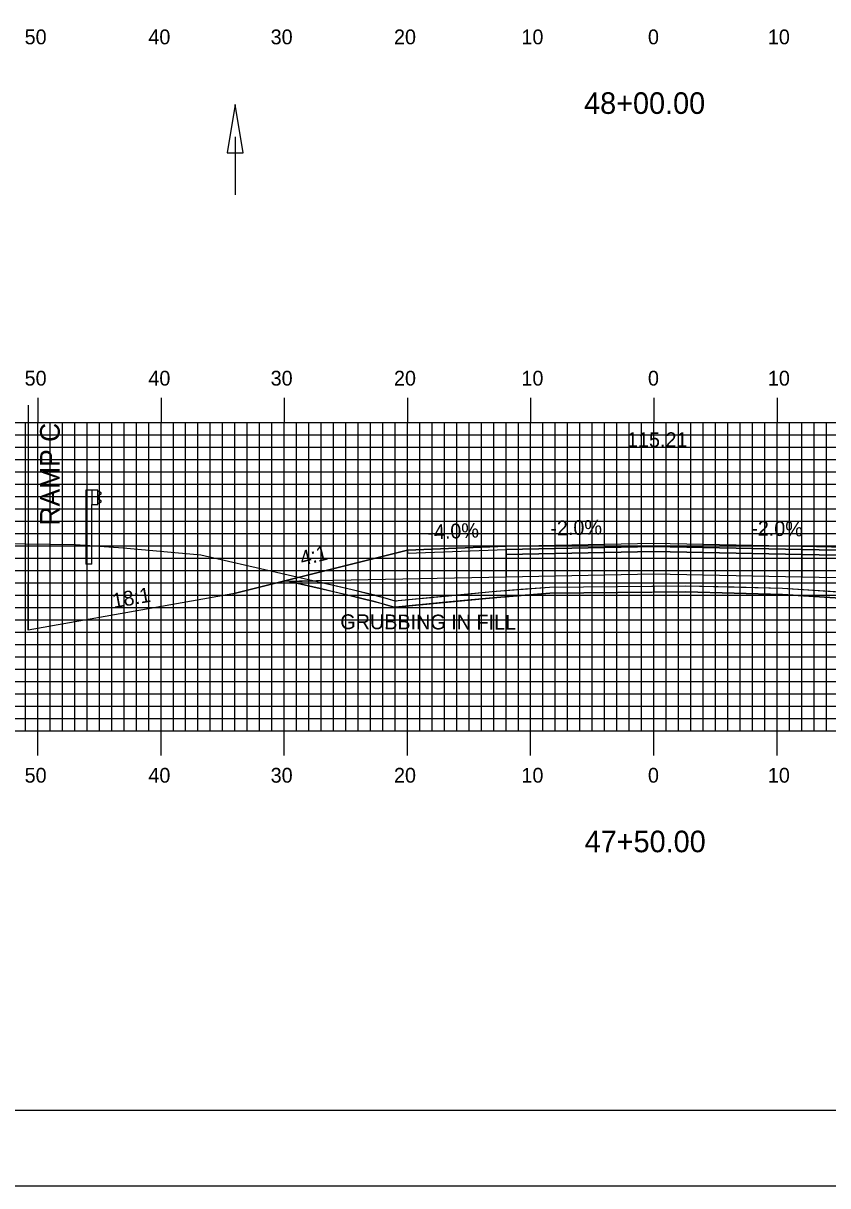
# Model space of a CAD drawing. Extents: x 1754708 to 1755051, y 442591 to 442811.
# Drawn here: x 1754822.3 to 1754887.6, y 442590.5 to 442684.8 of the extents above; entities that cross this region are included whole.
import ezdxf

# ---------------------------------------------------------------- set-up
doc = ezdxf.new("R2010")
doc.units = 0
for name, color, linetype in [('ANNOTATION', 7, 'Continuous'), ('BORDER', 7, 'Continuous'), ('D_Drainage_Ditch_Line', 7, 'Continuous'), ('D_Roadway_Centerline', 7, 'Continuous'), ('D_Roadway_Centerline_Text', 7, 'Continuous'), ('D_Roadway_Edge_Shoulder', 7, 'Continuous'), ('D_Roadway_Edge_TW', 7, 'Continuous'), ('D_Roadway_Pavement', 7, 'Continuous'), ('D_Roadway_SlopeLines', 7, 'Continuous'), ('D_Roadway_SubGrade', 7, 'Continuous'), ('GRUBBING IN FILL', 7, 'Continuous'), ('H_V ANNOTATION', 7, 'Continuous'), ('M_Guardrail', 7, 'Continuous'), ('MAJOR', 7, 'Continuous'), ('MINOR', 7, 'Continuous'), ('PLOT BOUNDARY', 7, 'Continuous'), ('S_Roadway_Centerline', 7, 'Continuous')]:
    doc.layers.add(name, color=color, linetype=linetype)

msp = doc.modelspace()

# ---------------------------------------------------------------- linework, layer by layer
at = {"layer": 'BORDER'}
msp.add_lwpolyline([(1754723.917, 442596.665), (1755043.917, 442596.665), (1755043.917, 442806.665), (1754723.917, 442806.665)], close=True, dxfattribs=at)
at = {"layer": 'D_Drainage_Ditch_Line'}
msp.add_line((1754839.529, 442675.611), (1754839.529, 442670.912), dxfattribs=at)
msp.add_lwpolyline([(1754838.873, 442674.298), (1754840.185, 442674.298), (1754839.529, 442678.235)], close=True, dxfattribs=at)
at = {"layer": 'D_Roadway_Centerline'}
msp.add_lwpolyline([(1754839.343, 442638.54), (1754843.343, 442639.54), (1754853.517, 442642.083), (1754861.517, 442642.403), (1754873.517, 442642.643), (1754885.517, 442642.403), (1754893.917, 442642.235), (1754901.917, 442641.915)], dxfattribs=at)
at = {"layer": 'D_Roadway_Edge_Shoulder'}
msp.add_lwpolyline([(1754861.517, 442642.403), (1754853.517, 442642.083), (1754853.517, 442641.833), (1754861.517, 442642.153)], close=True, dxfattribs=at)
at = {"layer": 'D_Roadway_Edge_TW'}
for points in [[(1754861.517, 442642.153), (1754861.517, 442642.403), (1754873.517, 442642.643), (1754885.517, 442642.403), (1754885.517, 442642.153), (1754873.517, 442642.393)], [(1754885.517, 442642.403), (1754893.917, 442642.235), (1754893.917, 442641.985), (1754885.517, 442642.153)]]:
    msp.add_lwpolyline(points, close=True, dxfattribs=at)
at = {"layer": 'D_Roadway_Pavement'}
for points in [[(1754861.517, 442641.736), (1754861.517, 442642.153), (1754873.517, 442642.393), (1754885.517, 442642.153), (1754885.517, 442641.736), (1754873.517, 442641.976)], [(1754885.517, 442642.153), (1754893.917, 442641.985), (1754893.917, 442641.568), (1754885.517, 442641.736)]]:
    msp.add_lwpolyline(points, close=True, dxfattribs=at)
at = {"layer": 'D_Roadway_SlopeLines'}
for p, q in [((1754822.747, 442635.606), (1754822.747, 442639.324)), ((1754839.343, 442638.54), (1754822.747, 442635.606))]:
    msp.add_line(p, q, dxfattribs=at)
msp.add_lwpolyline([(1754853.517, 442642.083), (1754839.343, 442638.54)], dxfattribs=at)
at = {"layer": 'D_Roadway_SubGrade'}
msp.add_line((1754822.747, 442653.844), (1754822.747, 442635.606), dxfattribs=at)
for points in [[(1754853.517, 442641.833), (1754861.517, 442642.153), (1754861.517, 442641.736), (1754861.517, 442639.903), (1754843.343, 442639.54), (1754853.517, 442642.083)], [(1754861.517, 442639.903), (1754861.517, 442641.736), (1754873.517, 442641.976), (1754885.517, 442641.736), (1754885.517, 442639.903), (1754873.517, 442640.143)], [(1754885.517, 442641.736), (1754893.917, 442641.568), (1754893.917, 442639.735), (1754885.517, 442639.903)]]:
    msp.add_lwpolyline(points, close=True, dxfattribs=at)
at = {"layer": 'GRUBBING IN FILL'}
for points in [[(1754843.956, 442639.552), (1754846.013, 442639.593), (1754849.044, 442638.898), (1754851.669, 442638.218), (1754852.494, 442637.976), (1754852.634, 442637.99), (1754852.774, 442638.004), (1754856.585, 442638.369), (1754860.396, 442638.734), (1754862.719, 442638.913), (1754865.043, 442639.092), (1754870.584, 442639.149), (1754873.517, 442639.179), (1754873.517, 442638.679), (1754870.592, 442638.649), (1754865.065, 442638.592), (1754862.752, 442638.414), (1754860.439, 442638.236), (1754856.631, 442637.871), (1754852.823, 442637.507), (1754852.447, 442637.469), (1754851.58, 442637.723), (1754846.442, 442638.982)], [(1754843.956, 442639.552), (1754846.013, 442639.593), (1754849.044, 442638.898), (1754851.669, 442638.218), (1754852.494, 442637.976), (1754852.634, 442637.99), (1754852.774, 442638.004), (1754856.585, 442638.369), (1754860.396, 442638.734), (1754862.719, 442638.913), (1754865.043, 442639.092), (1754870.584, 442639.149), (1754873.517, 442639.179), (1754873.517, 442638.679), (1754870.592, 442638.649), (1754865.065, 442638.592), (1754862.752, 442638.414), (1754860.439, 442638.236), (1754856.631, 442637.871), (1754852.823, 442637.507), (1754852.447, 442637.469), (1754851.58, 442637.723), (1754846.442, 442638.982)], [(1754873.517, 442639.179), (1754876.124, 442639.205), (1754880.045, 442639.102), (1754883.966, 442638.999), (1754889.322, 442638.663), (1754894.679, 442638.328), (1754899.258, 442637.968), (1754903.837, 442637.608), (1754910.777, 442637.359), (1754914.492, 442637.226), (1754914.492, 442636.725), (1754909.15, 442636.917), (1754903.808, 442637.109), (1754899.226, 442637.469), (1754894.644, 442637.829), (1754883.943, 442638.499), (1754880.032, 442638.602), (1754876.12, 442638.705), (1754873.517, 442638.679)], [(1754873.517, 442639.179), (1754876.124, 442639.205), (1754880.045, 442639.102), (1754883.966, 442638.999), (1754889.322, 442638.663), (1754894.679, 442638.328), (1754899.258, 442637.968), (1754903.837, 442637.608), (1754910.777, 442637.359), (1754914.492, 442637.226), (1754914.492, 442636.725), (1754909.15, 442636.917), (1754903.808, 442637.109), (1754899.226, 442637.469), (1754894.644, 442637.829), (1754883.943, 442638.499), (1754880.032, 442638.602), (1754876.12, 442638.705), (1754873.517, 442638.679)]]:
    msp.add_lwpolyline(points, close=True, dxfattribs=at)
msp.add_lwpolyline([(1754843.956, 442639.552), (1754848.929, 442638.411), (1754850.713, 442637.977), (1754852.447, 442637.469), (1754852.823, 442637.507), (1754860.439, 442638.236), (1754865.065, 442638.592), (1754876.12, 442638.705), (1754883.943, 442638.499), (1754894.644, 442637.829), (1754903.808, 442637.109), (1754914.492, 442636.725)], dxfattribs=at)
msp.add_lwpolyline([(1754843.956, 442639.552), (1754848.929, 442638.411), (1754850.713, 442637.977), (1754852.447, 442637.469), (1754852.823, 442637.507), (1754860.439, 442638.236), (1754865.065, 442638.592), (1754876.12, 442638.705), (1754883.943, 442638.499), (1754894.644, 442637.829), (1754903.808, 442637.109), (1754914.492, 442636.725)], dxfattribs=at)
at = {"layer": 'M_Guardrail'}
for p, q in [((1754827.408, 442646.956), (1754827.408, 442640.956)), ((1754827.899, 442646.956), (1754827.408, 442646.956)), ((1754828.389, 442646.956), (1754827.899, 442646.956)), ((1754827.899, 442646.956), (1754827.899, 442645.789)), ((1754828.389, 442645.789), (1754828.389, 442646.956)), ((1754828.389, 442646.883), (1754828.471, 442646.868)), ((1754828.488, 442646.861), (1754828.631, 442646.761)), ((1754828.471, 442645.876), (1754828.389, 442645.862)), ((1754828.402, 442646.418), (1754828.402, 442646.327)), ((1754828.631, 442646.618), (1754828.436, 442646.482)), ((1754828.436, 442646.262), (1754828.631, 442646.126)), ((1754828.631, 442645.983), (1754828.488, 442645.883)), ((1754827.899, 442640.956), (1754827.899, 442645.789)), ((1754827.899, 442645.789), (1754828.389, 442645.789)), ((1754827.899, 442640.956), (1754827.408, 442640.956))]:
    msp.add_line(p, q, dxfattribs=at)
for centre, major_axis, start_param, end_param in [((1754828.464, 442646.827), (0.0417, 0), 0.959931, 1.396263), ((1754828.481, 442646.418), (-0.0789, 0), 5.323254, 6.283185), ((1754828.481, 442646.327), (-0.0789, 0), 6.283185, 7.243116), ((1754828.464, 442645.917), (0.0417, 0), 4.886922, 5.323254), ((1754828.581, 442646.69), (0.0877, 0), 5.323254, 7.243116), ((1754828.581, 442646.055), (0.0877, 0), 5.323254, 7.243116)]:
    msp.add_ellipse(centre, major_axis=major_axis, ratio=0.995501, start_param=start_param, end_param=end_param, dxfattribs=at)
at = {"layer": 'MAJOR'}
for p, q in [((1754823.517, 442654.44), (1754823.517, 442652.436)), ((1754833.517, 442654.44), (1754833.517, 442652.436)), ((1754843.517, 442654.44), (1754843.517, 442652.436)), ((1754853.517, 442654.44), (1754853.517, 442652.436)), ((1754863.517, 442654.44), (1754863.517, 442652.436)), ((1754873.517, 442654.44), (1754873.517, 442652.436)), ((1754883.517, 442654.44), (1754883.517, 442652.436)), ((1754733.517, 442652.436), (1755013.517, 442652.436)), ((1754733.517, 442652.436), (1755013.517, 442652.436)), ((1754823.517, 442627.436), (1754823.517, 442652.436)), ((1754833.517, 442627.436), (1754833.517, 442652.436)), ((1754843.517, 442627.436), (1754843.517, 442652.436)), ((1754853.517, 442627.436), (1754853.517, 442652.436)), ((1754863.517, 442627.436), (1754863.517, 442652.436)), ((1754873.517, 442627.436), (1754873.517, 442652.436)), ((1754883.517, 442627.436), (1754883.517, 442652.436)), ((1754733.517, 442647.436), (1755013.517, 442647.436)), ((1754733.517, 442642.436), (1755013.517, 442642.436)), ((1754733.517, 442637.436), (1755013.517, 442637.436)), ((1754733.517, 442632.436), (1755013.517, 442632.436)), ((1754733.517, 442627.436), (1755013.517, 442627.436)), ((1754733.517, 442627.436), (1755013.517, 442627.436)), ((1754823.517, 442625.432), (1754823.517, 442627.436)), ((1754833.517, 442625.432), (1754833.517, 442627.436)), ((1754843.517, 442625.432), (1754843.517, 442627.436)), ((1754853.517, 442625.432), (1754853.517, 442627.436)), ((1754863.517, 442625.432), (1754863.517, 442627.436)), ((1754873.517, 442625.432), (1754873.517, 442627.436)), ((1754883.517, 442625.432), (1754883.517, 442627.436))]:
    msp.add_line(p, q, dxfattribs=at)
at = {"layer": 'MINOR'}
for p, q in [((1754822.517, 442627.436), (1754822.517, 442652.436)), ((1754824.517, 442627.436), (1754824.517, 442652.436)), ((1754825.517, 442627.436), (1754825.517, 442652.436)), ((1754826.517, 442627.436), (1754826.517, 442652.436)), ((1754827.517, 442627.436), (1754827.517, 442652.436)), ((1754828.517, 442627.436), (1754828.517, 442652.436)), ((1754829.517, 442627.436), (1754829.517, 442652.436)), ((1754830.517, 442627.436), (1754830.517, 442652.436)), ((1754831.517, 442627.436), (1754831.517, 442652.436)), ((1754832.517, 442627.436), (1754832.517, 442652.436)), ((1754834.517, 442627.436), (1754834.517, 442652.436)), ((1754835.517, 442627.436), (1754835.517, 442652.436)), ((1754836.517, 442627.436), (1754836.517, 442652.436)), ((1754837.517, 442627.436), (1754837.517, 442652.436)), ((1754838.517, 442627.436), (1754838.517, 442652.436)), ((1754839.517, 442627.436), (1754839.517, 442652.436)), ((1754840.517, 442627.436), (1754840.517, 442652.436)), ((1754841.517, 442627.436), (1754841.517, 442652.436)), ((1754842.517, 442627.436), (1754842.517, 442652.436)), ((1754844.517, 442627.436), (1754844.517, 442652.436)), ((1754845.517, 442627.436), (1754845.517, 442652.436)), ((1754846.517, 442627.436), (1754846.517, 442652.436)), ((1754847.517, 442627.436), (1754847.517, 442652.436)), ((1754848.517, 442627.436), (1754848.517, 442652.436)), ((1754849.517, 442627.436), (1754849.517, 442652.436)), ((1754850.517, 442627.436), (1754850.517, 442652.436)), ((1754851.517, 442627.436), (1754851.517, 442652.436)), ((1754852.517, 442627.436), (1754852.517, 442652.436)), ((1754854.517, 442627.436), (1754854.517, 442652.436)), ((1754855.517, 442627.436), (1754855.517, 442652.436)), ((1754856.517, 442627.436), (1754856.517, 442652.436)), ((1754857.517, 442627.436), (1754857.517, 442652.436)), ((1754858.517, 442627.436), (1754858.517, 442652.436)), ((1754859.517, 442627.436), (1754859.517, 442652.436)), ((1754860.517, 442627.436), (1754860.517, 442652.436)), ((1754861.517, 442627.436), (1754861.517, 442652.436)), ((1754862.517, 442627.436), (1754862.517, 442652.436)), ((1754864.517, 442627.436), (1754864.517, 442652.436)), ((1754865.517, 442627.436), (1754865.517, 442652.436)), ((1754866.517, 442627.436), (1754866.517, 442652.436)), ((1754867.517, 442627.436), (1754867.517, 442652.436)), ((1754868.517, 442627.436), (1754868.517, 442652.436)), ((1754869.517, 442627.436), (1754869.517, 442652.436)), ((1754870.517, 442627.436), (1754870.517, 442652.436)), ((1754871.517, 442627.436), (1754871.517, 442652.436)), ((1754872.517, 442627.436), (1754872.517, 442652.436)), ((1754874.517, 442627.436), (1754874.517, 442652.436)), ((1754875.517, 442627.436), (1754875.517, 442652.436)), ((1754876.517, 442627.436), (1754876.517, 442652.436)), ((1754877.517, 442627.436), (1754877.517, 442652.436)), ((1754878.517, 442627.436), (1754878.517, 442652.436)), ((1754879.517, 442627.436), (1754879.517, 442652.436)), ((1754880.517, 442627.436), (1754880.517, 442652.436)), ((1754881.517, 442627.436), (1754881.517, 442652.436)), ((1754882.517, 442627.436), (1754882.517, 442652.436)), ((1754884.517, 442627.436), (1754884.517, 442652.436)), ((1754885.517, 442627.436), (1754885.517, 442652.436)), ((1754886.517, 442627.436), (1754886.517, 442652.436)), ((1754887.517, 442627.436), (1754887.517, 442652.436)), ((1754733.517, 442651.436), (1755013.517, 442651.436)), ((1754733.517, 442650.436), (1755013.517, 442650.436)), ((1754733.517, 442649.436), (1755013.517, 442649.436)), ((1754733.517, 442648.436), (1755013.517, 442648.436)), ((1754733.517, 442646.436), (1755013.517, 442646.436)), ((1754733.517, 442645.436), (1755013.517, 442645.436)), ((1754733.517, 442644.436), (1755013.517, 442644.436)), ((1754733.517, 442643.436), (1755013.517, 442643.436)), ((1754733.517, 442641.436), (1755013.517, 442641.436)), ((1754733.517, 442640.436), (1755013.517, 442640.436)), ((1754733.517, 442639.436), (1755013.517, 442639.436)), ((1754733.517, 442638.436), (1755013.517, 442638.436)), ((1754733.517, 442636.436), (1755013.517, 442636.436)), ((1754733.517, 442635.436), (1755013.517, 442635.436)), ((1754733.517, 442634.436), (1755013.517, 442634.436)), ((1754733.517, 442633.436), (1755013.517, 442633.436)), ((1754733.517, 442631.436), (1755013.517, 442631.436)), ((1754733.517, 442630.436), (1755013.517, 442630.436)), ((1754733.517, 442629.436), (1755013.517, 442629.436)), ((1754733.517, 442628.436), (1755013.517, 442628.436))]:
    msp.add_line(p, q, dxfattribs=at)
at = {"layer": 'PLOT BOUNDARY'}
msp.add_lwpolyline([(1754707.731, 442590.547), (1755047.731, 442590.547), (1755047.731, 442810.547), (1754707.731, 442810.547)], close=True, dxfattribs=at)
at = {"layer": 'S_Roadway_Centerline'}
msp.add_lwpolyline([(1754812.363, 442642.73), (1754826.567, 442642.536), (1754830.457, 442642.285), (1754836.76, 442641.715), (1754849.044, 442638.898), (1754850.843, 442638.46), (1754852.494, 442637.976), (1754852.774, 442638.004), (1754860.396, 442638.734), (1754865.043, 442639.092), (1754876.124, 442639.205), (1754883.966, 442638.999), (1754894.679, 442638.328), (1754903.837, 442637.608), (1754917.718, 442637.11), (1754922.652, 442636.901), (1754925.871, 442636.792), (1754941.98, 442636.307), (1754947.765, 442636.036), (1754956.702, 442635.659)], dxfattribs=at)

# ---------------------------------------------------------------- texts
at = {"layer": 'ANNOTATION'}
for s, height, rotation, p in [('RAMP C', 1.6, 90, (1754825.3, 442644.089)), ('-4.0%', 1.2, 2.29061, (1754855.149, 442642.95)), ('-2.0%', 1.2, 1.14576, (1754865.124, 442643.276)), ('-2.0%', 1.2, 358.85424, (1754881.404, 442643.286)), ('4:1', 1.2, 14.03624, (1754844.966, 442640.807)), ('18:1', 1.2, 10.02236, (1754829.674, 442637.373))]:
    msp.add_text(s, height=height, rotation=rotation, dxfattribs=at).set_placement(p)
at = {"layer": 'D_Roadway_Centerline'}
for s, p in [('C', (1754873.512, 442642.643)), ('L', (1754873.517, 442642.636))]:
    msp.add_text(s, height=0.0146, dxfattribs=at).set_placement(p)
at = {"layer": 'D_Roadway_Centerline_Text'}
msp.add_text('115.21', height=1.2, dxfattribs=at).set_placement((1754871.334, 442650.448))
at = {"layer": 'GRUBBING IN FILL'}
msp.add_text('GRUBBING IN FILL', height=1.2, rotation=359.81416, dxfattribs=at).set_placement((1754848.065, 442635.687))
at = {"layer": 'H_V ANNOTATION'}
for s, height, p in [('50', 1.2, (1754822.447, 442683.112)), ('40', 1.2, (1754832.49, 442683.112)), ('30', 1.2, (1754842.415, 442683.112)), ('20', 1.2, (1754852.425, 442683.112)), ('10', 1.2, (1754862.768, 442683.112)), ('0', 1.2, (1754873.036, 442683.112)), ('10', 1.2, (1754882.768, 442683.112)), ('48+00.00', 1.75, (1754867.853, 442677.468)), ('50', 1.2, (1754822.447, 442655.436)), ('40', 1.2, (1754832.49, 442655.436)), ('30', 1.2, (1754842.415, 442655.436)), ('20', 1.2, (1754852.425, 442655.436)), ('10', 1.2, (1754862.768, 442655.436)), ('0', 1.2, (1754873.036, 442655.436)), ('10', 1.2, (1754882.768, 442655.436)), ('50', 1.2, (1754822.447, 442623.236)), ('40', 1.2, (1754832.49, 442623.236)), ('30', 1.2, (1754842.415, 442623.236)), ('20', 1.2, (1754852.425, 442623.236)), ('10', 1.2, (1754862.768, 442623.236)), ('0', 1.2, (1754873.036, 442623.236)), ('10', 1.2, (1754882.768, 442623.236)), ('47+50.00', 1.75, (1754867.899, 442617.592))]:
    msp.add_text(s, height=height, dxfattribs=at).set_placement(p)

doc.saveas('drawing.dxf')
